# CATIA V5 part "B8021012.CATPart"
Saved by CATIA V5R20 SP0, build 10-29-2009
Part number: B8021012
Revision: 3
Definition: design
Nomenclature: B8021012
Source: made
Description: NOT SPECIFIED
Bounding box of the stored display mesh (mm): x -12 to 12, y -12 to 12, z -9 to 12
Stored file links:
  C:\Users\Utente\Desktop\3D files B802\B8021012.CATPart
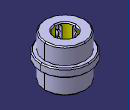
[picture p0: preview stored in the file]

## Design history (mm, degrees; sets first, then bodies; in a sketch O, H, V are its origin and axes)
Body1 "MANIFOLD_SOLID_BREP #38" (main body)
  Solid1: solid without history
Body2 "MANIFOLD_SOLID_BREP #76"
  Solid2: solid without history
Body3 "MANIFOLD_SOLID_BREP #114"
  Solid3: solid without history
Body4 "MANIFOLD_SOLID_BREP #152"
  Solid4: solid without history
Body5 "MANIFOLD_SOLID_BREP #190"
  Solid5: solid without history
Body6 "MANIFOLD_SOLID_BREP #228"
  Solid6: solid without history
Body7 "MANIFOLD_SOLID_BREP #266"
  Solid7: solid without history
Body8 "MANIFOLD_SOLID_BREP #1739"
  Solid8: solid without history
Body9 "MANIFOLD_SOLID_BREP #1777"
  Solid9: solid without history
Body10 "MANIFOLD_SOLID_BREP #1815"
  Solid10: solid without history
Body11 "MANIFOLD_SOLID_BREP #1853"
  Solid11: solid without history
Body12 "MANIFOLD_SOLID_BREP #1891"
  Solid12: solid without history
Body13 "MANIFOLD_SOLID_BREP #1929"
  Solid13: solid without history
Body14 "MANIFOLD_SOLID_BREP #1967"
  Solid14: solid without history
Body15 "MANIFOLD_SOLID_BREP #2005"
  Solid15: solid without history
Body16 "MANIFOLD_SOLID_BREP #2043"
  Solid16: solid without history
Body17 "MANIFOLD_SOLID_BREP #2081"
  Solid17: solid without history
Body18 "MANIFOLD_SOLID_BREP #2119"
  Solid18: solid without history
Body19 "MANIFOLD_SOLID_BREP #2157"
  Solid19: solid without history
Body20 "MANIFOLD_SOLID_BREP #2195"
  Solid20: solid without history
Body21 "MANIFOLD_SOLID_BREP #2233"
  Solid21: solid without history
Body22 "MANIFOLD_SOLID_BREP #2271"
  Solid22: solid without history
Body23 "MANIFOLD_SOLID_BREP #2309"
  Solid23: solid without history
Body24 "MANIFOLD_SOLID_BREP #2347"
  Solid24: solid without history
Body25 "MANIFOLD_SOLID_BREP #2385"
  Solid25: solid without history
Body26 "MANIFOLD_SOLID_BREP #2423"
  Solid26: solid without history
Body27 "MANIFOLD_SOLID_BREP #2461"
  Solid27: solid without history
Body28 "MANIFOLD_SOLID_BREP #2499"
  Solid28: solid without history
Body29 "MANIFOLD_SOLID_BREP #2537"
  Solid29: solid without history
Body30 "MANIFOLD_SOLID_BREP #2575"
  Solid30: solid without history
Body31 "MANIFOLD_SOLID_BREP #2613"
  Solid31: solid without history
Body32 "MANIFOLD_SOLID_BREP #2651"
  Solid32: solid without history
Body33 "MANIFOLD_SOLID_BREP #2689"
  Solid33: solid without history
Body34 "MANIFOLD_SOLID_BREP #2727"
  Solid34: solid without history
Body35 "MANIFOLD_SOLID_BREP #2765"
  Solid35: solid without history
Body36 "MANIFOLD_SOLID_BREP #2803"
  Solid36: solid without history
